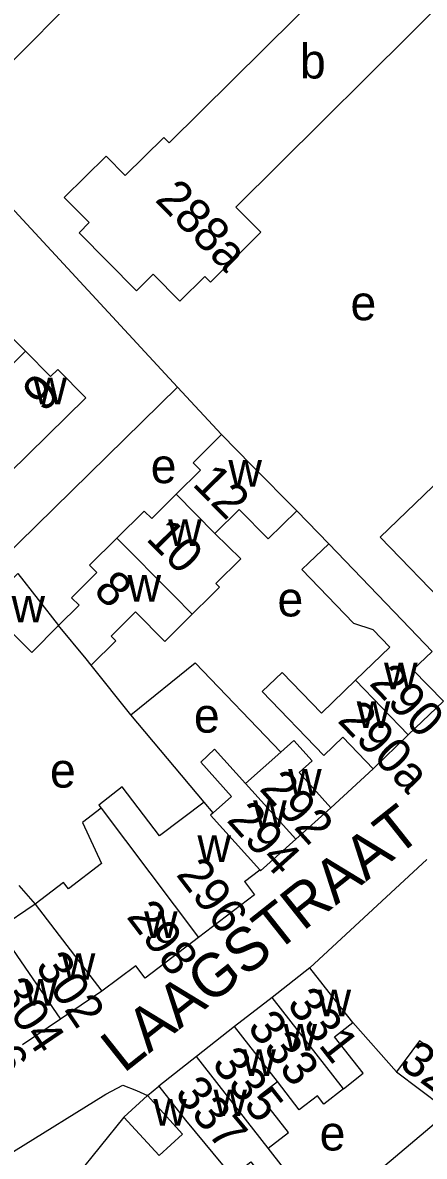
# Model space of a CAD drawing. Extents: x 159045 to 160918, y 380454 to 382516.
# Drawn here: x 160115.5 to 160161.8, y 381685.3 to 381816.1 of the extents above; entities that cross this region are included whole.
import ezdxf

# ---------------------------------------------------------------- set-up
doc = ezdxf.new("R2010")
doc.units = 0
for name, color, linetype in [('BLT_Basislijn', 7, 'Continuous'), ('BLT_Bebouwing', 7, 'Continuous'), ('BLT_Centroide', 7, 'Continuous'), ('BLT_Huisnummer', 7, 'Continuous'), ('BLT_Huisnummer_ tussenligend', 7, 'Continuous'), ('BLT_Onderverdeling_panden', 7, 'Continuous'), ('BLT_Straatnaam', 7, 'Continuous')]:
    doc.layers.add(name, color=color, linetype=linetype)

msp = doc.modelspace()

# ---------------------------------------------------------------- linework, layer by layer
at = {"layer": 'BLT_Basislijn'}
for p, q in [((160112.99, 381754.09), (160133.33, 381774.04)), ((160138.39, 381768.58), (160133.33, 381774.04)), ((160163.77, 381763.56), (160156.7, 381756.74)), ((160147.08, 381759.78), (160150.79, 381755.99)), ((160156.7, 381756.74), (160168.97, 381744.03)), ((160127.94, 381736.25), (160123.37, 381741.99)), ((160136.39, 381726.19), (160127.94, 381736.25)), ((160155.89, 381730.04), (160150.99, 381725.53)), ((160162.06, 381719.58), (160148.59, 381707.09)), ((160115.02, 381716.55), (160116.89, 381714.43)), ((160158.59, 381695.07), (160153.54, 381700.76)), ((160129.85, 381692.34), (160131.15, 381693.44)), ((160152.83, 381680.58), (160164.15, 381690.11)), ((160127.14, 381689.85), (160121.67, 381683.08))]:
    msp.add_line(p, q, dxfattribs=at)
for points in [[(160133.33, 381774.04), (160106.06, 381803.48), (160106.09, 381803.83), (160107.13, 381804.49), (160128.43, 381825.89)], [(160127.94, 381736.25), (160135.35, 381742.25), (160145.22, 381731.95)], [(160103.73, 381679.28), (160125.07, 381692.52), (160127.01, 381693.56), (160128.59, 381692.94), (160129.85, 381692.34)]]:
    msp.add_lwpolyline(points, dxfattribs=at)
at = {"layer": 'BLT_Bebouwing'}
for p, q in [((160137.19, 381750), (160135.02, 381747.85)), ((160119.59, 381746.54), (160121.97, 381748.89)), ((160159.93, 381733.93), (160163.98, 381737.82)), ((160155.89, 381730.04), (160159.93, 381733.93)), ((160145.22, 381731.95), (160141.18, 381728.32)), ((160150.99, 381725.53), (160146.95, 381721.9)), ((160146.95, 381721.9), (160142.91, 381718.27)), ((160148.59, 381707.09), (160144.22, 381703.67)), ((160124.59, 381704.4), (160119.84, 381701.17)), ((160144.22, 381703.67), (160139.89, 381700.29)), ((160119.84, 381701.17), (160115.45, 381698.2)), ((160139.89, 381700.29), (160135.5, 381696.85)), ((160135.5, 381696.85), (160131.15, 381693.44)), ((160158.59, 381695.07), (160163.88, 381691.09)), ((160127.14, 381689.85), (160129.85, 381692.34))]:
    msp.add_line(p, q, dxfattribs=at)
for points in [[(160165.17, 381819.73), (160140.05, 381794.81), (160142.94, 381791.9), (160137.12, 381786.13), (160136.46, 381786.81), (160133.6, 381783.97), (160130.52, 381787.08), (160128.59, 381785.16), (160121.96, 381791.84), (160123.15, 381793.01), (160120.24, 381795.9), (160125.11, 381800.68), (160127.3, 381798.45), (160131.73, 381802.84), (160132.35, 381802.21), (160150.58, 381820.29)], [(160115.78, 381778.18), (160110.86, 381783.1), (160111.71, 381783.94), (160108.54, 381787.16)], [(160113.91, 381764.12), (160122.74, 381772.81), (160119.51, 381776.09), (160118.67, 381775.25), (160115.78, 381778.18)], [(160138.39, 381768.58), (160135.12, 381765.31), (160135.97, 381764.46), (160133.15, 381761.69)], [(160147.08, 381759.78), (160141.9, 381765.02), (160138.39, 381768.58)], [(160133.15, 381761.69), (160130.34, 381758.91), (160129.48, 381759.75), (160126.32, 381756.62)], [(160147.08, 381759.78), (160143.79, 381756.53), (160140.43, 381759.94), (160137.61, 381757.16)], [(160137.61, 381757.16), (160140.61, 381754.24), (160137.75, 381751.41), (160138.18, 381750.98), (160137.19, 381750)], [(160126.32, 381756.62), (160123.17, 381753.5), (160124.02, 381752.65), (160121.35, 381750)], [(160150.79, 381755.99), (160148.47, 381753.77), (160147.67, 381753.01), (160153.61, 381746.82), (160155.85, 381746.08), (160157.81, 381744.04), (160153.86, 381740.24)], [(160162.68, 381743.57), (160159.23, 381747.18), (160150.79, 381755.99)], [(160119.59, 381746.54), (160116.5, 381743.43), (160111.13, 381748.79), (160114.9, 381752.56)], [(160114.9, 381752.56), (160119.59, 381746.54)], [(160121.97, 381748.89), (160121.11, 381749.76), (160121.35, 381750)], [(160135.02, 381747.85), (160131.85, 381744.72), (160128.48, 381748.14), (160125.65, 381745.34)], [(160123.37, 381741.99), (160122.79, 381742.7), (160119.59, 381746.54)], [(160125.65, 381745.34), (160126.2, 381744.79), (160123.37, 381741.99)], [(160163.98, 381737.82), (160160.46, 381741.45), (160162.68, 381743.57)], [(160153.86, 381740.24), (160149.91, 381736.45), (160145.39, 381741.15), (160143.09, 381738.94), (160150.18, 381731.56), (160152.39, 381733.68), (160155.89, 381730.04)], [(160150.99, 381725.53), (160147.65, 381729.25), (160147.35, 381729.59), (160148.84, 381730.95), (160146.73, 381733.3), (160145.22, 381731.95)], [(160141.18, 381728.32), (160137.6, 381732.28), (160136.01, 381730.8), (160139.54, 381726.84), (160137.42, 381724.94)], [(160136.39, 381726.19), (160131.26, 381722.28), (160126.95, 381727.93), (160124.23, 381725.85), (160124.52, 381725.48)], [(160124.52, 381725.48), (160122.37, 381723.84), (160124.57, 381719.09)], [(160137.42, 381724.94), (160136.39, 381726.19)], [(160137.42, 381724.94), (160137.14, 381724.69), (160142.82, 381718.38)], [(160124.57, 381719.09), (160120.75, 381716.18), (160120.19, 381716.91), (160116.89, 381714.43)], [(160141.05, 381717.02), (160142.82, 381718.38)], [(160142.82, 381718.38), (160142.91, 381718.27)], [(160141.05, 381717.02), (160142.2, 381715.51), (160135.74, 381710.59)], [(160116.89, 381714.43), (160112.68, 381711.58), (160113.87, 381709.83)], [(160135.74, 381710.59), (160129.59, 381705.89), (160128.52, 381707.29)], [(160128.52, 381707.29), (160124.59, 381704.4)], [(160153.54, 381700.76), (160151.67, 381703.15), (160148.59, 381707.09)], [(160152.46, 381693.13), (160154.73, 381694.91), (160151.43, 381699.11), (160153.54, 381700.76)], [(160166.54, 381694.78), (160161.23, 381698.66), (160158.59, 381695.07)], [(160131.15, 381693.44), (160134.23, 381689.51), (160139.62, 381683.01)], [(160143.78, 381686.27), (160146.11, 381688.1), (160142.78, 381692.34), (160144.84, 381693.96)], [(160152.46, 381693.13), (160150.2, 381691.36), (160149.47, 381692.3), (160147.37, 381690.68), (160144.84, 381693.96)], [(160129.85, 381692.34), (160133.91, 381687.9), (160131.2, 381685.42), (160127.14, 381689.85)], [(160139.62, 381683.01), (160141.76, 381684.69), (160143.53, 381682.44), (160145.56, 381684), (160143.78, 381686.27)]]:
    msp.add_lwpolyline(points, dxfattribs=at)
at = {"layer": 'BLT_Onderverdeling_panden'}
for p, q in [((160111.22, 381773.69), (160115.78, 381778.18)), ((160133.15, 381761.69), (160137.61, 381757.16)), ((160126.32, 381756.62), (160132.89, 381750)), ((160132.89, 381750), (160135.02, 381747.85)), ((160153.86, 381740.24), (160159.93, 381733.93)), ((160141.18, 381728.32), (160146.95, 381721.9)), ((160124.52, 381725.48), (160135.74, 381710.59)), ((160116.89, 381714.43), (160124.59, 381704.4)), ((160113.87, 381709.83), (160119.84, 381701.17)), ((160152.46, 381693.13), (160144.22, 381703.67)), ((160144.84, 381693.96), (160139.89, 381700.29)), ((160143.78, 381686.27), (160135.5, 381696.85))]:
    msp.add_line(p, q, dxfattribs=at)

# ---------------------------------------------------------------- texts
at = {"layer": 'BLT_Centroide'}
for s, p in [('b', (160147.44, 381809.64)), ('e', (160153.27, 381781.76)), ('w', (160116.7, 381772.06)), ('e', (160130.23, 381762.97)), ('w', (160139.19, 381762.56)), ('w', (160132.25, 381755.73)), ('w', (160127.56, 381749.31)), ('e', (160144.85, 381747.6)), ('w', (160114.18, 381746.9)), ('w', (160157.14, 381739.19)), ('e', (160135.21, 381734.2)), ('w', (160153.99, 381734.74)), ('e', (160118.61, 381727.86)), ('w', (160146.08, 381726.94)), ('w', (160142.05, 381723.3)), ('w', (160135.62, 381719.28)), ('w', (160129.47, 381710.53)), ('w', (160119.98, 381705.69)), ('w', (160115.59, 381702.7)), ('w', (160149.47, 381701.47)), ('w', (160145.55, 381697.53)), ('w', (160140.8, 381694.59)), ('w', (160137.47, 381689.97)), ('w', (160130.53, 381688.88)), ('e', (160149.71, 381686.01))]:
    msp.add_text(s, height=4, dxfattribs=at).set_placement(p)
at = {"layer": 'BLT_Huisnummer'}
for s, rotation, p in [('288a', 314.7683, (160130.6, 381795.57)), ('9', 44.5389, (160117.89, 381771.02)), ('12', 314.5791, (160134.92, 381762.78)), ('10', 314.7605, (160129.57, 381756.48)), ('8', 316.0134, (160123.49, 381750.4)), ('290', 313.8528, (160155.32, 381739.8)), ('290a', 314.0613, (160151.66, 381735.52)), ('292', 311.9517, (160142.66, 381727.66)), ('294', 311.9523, (160138.88, 381724.05)), ('296', 307.3307, (160133.07, 381717.82)), ('298', 307.3145, (160127.35, 381712.95)), ('302', 304.1451, (160116.83, 381707.23)), ('331', 308.0473, (160145.83, 381702.82)), ('306', 304.1451, (160108.06, 381701.5)), ('329', 323.9249, (160158.72, 381695.75)), ('337', 309.6603, (160132.89, 381692.51))]:
    msp.add_text(s, height=4, rotation=rotation, dxfattribs=at).set_placement(p)
at = {"layer": 'BLT_Huisnummer_ tussenligend'}
for s, rotation, p in [('304', 304.1451, (160112.25, 381704.24)), ('333', 308.0473, (160141.27, 381700.17)), ('335', 308.0621, (160137.17, 381695.97))]:
    msp.add_text(s, height=4, rotation=rotation, dxfattribs=at).set_placement(p)
at = {"layer": 'BLT_Straatnaam'}
msp.add_text('LAAGSTRAAT', height=5, rotation=38.396, dxfattribs=at).set_placement((160127.11, 381694.84))

doc.saveas('drawing.dxf')
